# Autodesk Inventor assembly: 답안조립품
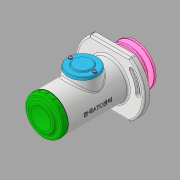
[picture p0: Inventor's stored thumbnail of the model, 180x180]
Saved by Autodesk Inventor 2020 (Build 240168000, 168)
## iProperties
Created: 2022-05
Part Number: 답안조립품
Document SubType Name: Assembly
Designer: User
Author: User
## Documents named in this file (22)
- C:\Users\User\Desktop\720506V1015\답안조립품.iam
- C:\Users\User\Desktop\720506V1015\본체.ipt
- C:\Users\User\Desktop\720506V1015\V-벨트풀리.ipt
- C:\Users\User\Desktop\720506V1015\개스킷.ipt
- C:\Users\User\Desktop\720506V1015\너트 M10.ipt
- C:\Users\User\Desktop\720506V1015\멈춤나사 M3.ipt
- C:\Users\User\Desktop\720506V1015\멈춤링 15 x 1.ipt
- C:\Users\User\Desktop\720506V1015\멈춤링 35 x 1.6.ipt
- C:\Users\User\Desktop\720506V1015\베어링 6202.ipt
- C:\Users\User\Desktop\720506V1015\볼트 M4 x 10.ipt
- C:\Users\User\Desktop\720506V1015\부시1.ipt
- C:\Users\User\Desktop\720506V1015\부시2.ipt
- C:\Users\User\Desktop\720506V1015\사이드 커버.ipt
- 사이드 커버.ipt
- C:\Users\User\Desktop\720506V1015\십자볼트 M3 x 10.ipt
- C:\Users\User\Desktop\720506V1015\오일 실 15 x 30 x 7.ipt
- C:\Users\User\Desktop\720506V1015\와셔 3 x 6.ipt
- C:\Users\User\Desktop\720506V1015\와셔 4 x 16.ipt
- C:\Users\User\Desktop\720506V1015\와셔 10 x 21.ipt
- C:\Users\User\Desktop\720506V1015\축.ipt
- C:\Users\User\Desktop\720506V1015\키 4 x 4.ipt
- C:\Users\User\Desktop\720506V1015\탑 커버.ipt
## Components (3 placed, 3 different names)
1. 개스킷:1
2. V-벨트풀리:1
3. ISO 4017 M4 x 10:1 — 각도:6
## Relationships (1: Angle 1)
- 각도:6 [Angle]: ISO 4017 M4 x 10:1
